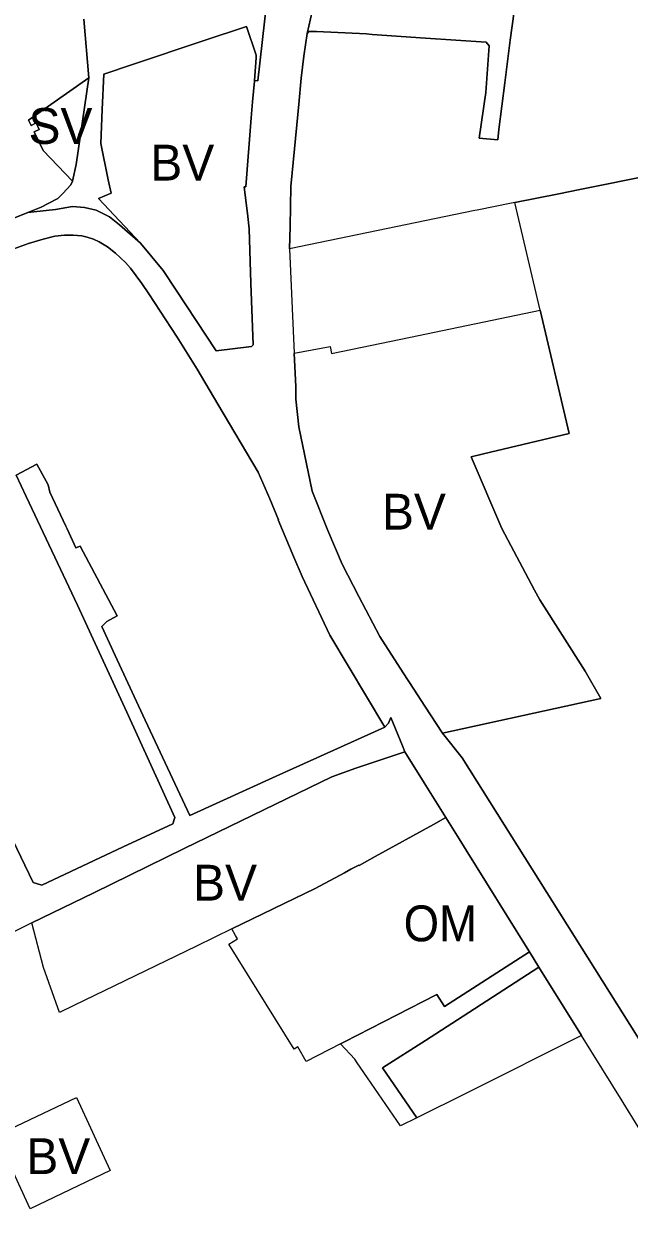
# Model space of a CAD drawing. Extents: x -650451 to -642268, y -1075216 to -1066610.
# Drawn here: x -648281.9 to -648079.4, y -1067506.5 to -1067105.4 of the extents above; entities that cross this region are included whole.
import ezdxf

# ---------------------------------------------------------------- set-up
doc = ezdxf.new("R2010")
doc.units = 0
doc.header["$LTSCALE"] = 4.8
for name, color, linetype, lineweight in [('12', 7, 'Continuous', 13), ('15', 7, 'Continuous', 13), ('19', 7, 'Continuous', 13), ('24', 7, 'Continuous', 13), ('3', 7, 'Continuous', 13), ('46', 7, 'Continuous', 13)]:
    doc.layers.add(name, color=color, linetype=linetype, lineweight=lineweight)
doc.layers.add('62', color=7, linetype='Continuous')

msp = doc.modelspace()

# ---------------------------------------------------------------- linework, layer by layer
at = {"layer": '12'}
for points in [[(-648212.32, -1067408.39), (-648184.44, -1067394.86), (-648174.63, -1067389.58), (-648172.45, -1067388.4), (-648169.81, -1067386.98), (-648169.73, -1067387.11), (-648164.35, -1067384.16), (-648144.8, -1067373.45), (-648140.65, -1067371.06)], [(-648140.65, -1067371.06), (-648136.27, -1067378.19), (-648133.9, -1067381.99), (-648113.46, -1067414.8), (-648112.7, -1067416.03)], [(-648175.94, -1067446.89), (-648187.44, -1067452.8), (-648190.23, -1067447.83), (-648191.46, -1067448.59), (-648213.34, -1067413.46), (-648210.48, -1067411.68), (-648211.08, -1067410.6), (-648212.32, -1067408.39)], [(-648112.7, -1067416.03), (-648141.17, -1067434.4), (-648143.66, -1067430.3), (-648157.23, -1067437.28), (-648174.64, -1067446.22), (-648175.94, -1067446.89)]]:
    msp.add_lwpolyline(points, dxfattribs=at)
at = {"layer": '15'}
msp.add_line((-648187.15, -1067108.56), (-648185.48, -1067101.2), dxfattribs=at)
for points in [[(-648120.26, -1067073.08), (-648118.18, -1067057.64), (-648115.89, -1067041.73), (-648115.37, -1067037.82), (-648109.4, -1067038.4), (-648111.32, -1067052.86), (-648113.21, -1067067.35), (-648115.19, -1067081.63), (-648117.16, -1067096.34), (-648119.2, -1067110.85), (-648121, -1067125.08), (-648122.95, -1067140.69), (-648123.31, -1067144.17), (-648129.51, -1067143.6), (-648127.29, -1067128.4), (-648126.24, -1067112.71), (-648127.23, -1067111.47), (-648147.53, -1067110.1), (-648165.4, -1067108.88), (-648167.25, -1067108.76), (-648183.98, -1067107.89), (-648186.54, -1067107.89), (-648187.15, -1067108.56)], [(-648200.58, -1067097.82), (-648203.67, -1067124.43), (-648204.77, -1067124.3)], [(-648260.23, -1067123.43), (-648261.9, -1067103.74)], [(-648204.77, -1067124.3), (-648204.18, -1067116.76), (-648204.14, -1067115.83), (-648207.42, -1067106.27), (-648221.9, -1067111.09), (-648245.64, -1067119), (-648255.23, -1067122.19), (-648255.75, -1067134.09), (-648256.24, -1067145.39), (-648253.68, -1067157.6), (-648252.74, -1067162.04), (-648257.01, -1067163.83), (-648242.92, -1067178.79), (-648249.92, -1067172.63), (-648253.32, -1067169.98), (-648257.72, -1067167.76), (-648261.61, -1067166.88)], [(-648265.69, -1067158.05), (-648264.39, -1067152.4), (-648260.23, -1067123.43)], [(-648280.63, -1067168.54), (-648276.15, -1067166.76), (-648273.82, -1067165.52), (-648270.63, -1067163.83), (-648268.87, -1067162.19), (-648266.18, -1067159.3), (-648265.69, -1067158.05)], [(-648261.61, -1067166.88), (-648265.72, -1067166.46), (-648271.34, -1067167.56), (-648278.67, -1067168.33), (-648280.63, -1067168.54)], [(-648288.48, -1067372.88), (-648278.83, -1067392.79), (-648275.98, -1067393.72), (-648248.74, -1067380.92), (-648232.11, -1067373.17), (-648231.37, -1067371.1), (-648247.54, -1067335.81), (-648264.05, -1067299.96), (-648281.13, -1067263.61), (-648284.52, -1067256.43), (-648277.56, -1067252.8), (-648273.81, -1067259.75), (-648273.21, -1067262.16), (-648267.92, -1067273.51), (-648267.51, -1067274.4), (-648264.52, -1067280.81), (-648263.08, -1067280.18), (-648250.71, -1067303.55), (-648254.2, -1067305.44), (-648255.84, -1067307.08), (-648251.41, -1067316.83), (-648242.12, -1067336.79), (-648226.42, -1067370.37), (-648197.5, -1067357.28), (-648161.07, -1067340.8)], [(-648161.07, -1067340.8), (-648159.92, -1067339.44), (-648159.09, -1067337.57)], [(-648159.09, -1067337.57), (-648155.18, -1067347.12), (-648154.39, -1067349.06)], [(-648154.39, -1067349.06), (-648170.82, -1067354.57), (-648178.86, -1067357.46), (-648228.27, -1067381.48), (-648258.57, -1067396.29), (-648279.24, -1067406.38), (-648285.08, -1067409.24)], [(-648175.94, -1067446.89), (-648174.64, -1067446.22), (-648157.23, -1067437.28), (-648143.66, -1067430.3), (-648141.17, -1067434.4), (-648112.7, -1067416.03), (-648109.53, -1067421.13)], [(-648109.53, -1067421.13), (-648136.84, -1067438.83), (-648147.52, -1067445.69), (-648161.9, -1067454.92), (-648150.46, -1067471.66)], [(-648150.46, -1067471.66), (-648155.85, -1067474.35), (-648166.97, -1067458.18), (-648170.38, -1067453.23), (-648171.21, -1067452.01), (-648175.94, -1067446.89)]]:
    msp.add_lwpolyline(points, dxfattribs=at)
at = {"layer": '19'}
for points in [[(-648265.69, -1067158.05), (-648275.47, -1067147.81), (-648278.49, -1067141.5), (-648276.78, -1067140.68), (-648277.82, -1067138.52), (-648279.53, -1067139.34), (-648280.36, -1067137.63), (-648260.23, -1067123.43)], [(-648260.23, -1067123.43), (-648264.39, -1067152.4), (-648265.69, -1067158.05)]]:
    msp.add_lwpolyline(points, dxfattribs=at)
at = {"layer": '24'}
for points in [[(-648182.63, -1067072.9), (-648183.67, -1067082.49), (-648183.16, -1067082.6), (-648183.92, -1067088.24), (-648185.48, -1067101.2), (-648187.15, -1067108.56)], [(-648204.77, -1067124.3), (-648203.67, -1067124.43), (-648200.58, -1067097.82)], [(-648187.15, -1067108.56), (-648188.2, -1067116.19), (-648189.09, -1067123.6), (-648189.96, -1067132.29), (-648190.59, -1067139.22), (-648192.56, -1067159.86), (-648192.86, -1067173.21), (-648193.02, -1067180.66), (-648191.439, -1067215.62)], [(-648205.72, -1067213.38), (-648205.23, -1067212.8), (-648205.95, -1067192.14), (-648206.51, -1067174.01), (-648206.95, -1067169.86), (-648208.19, -1067159.9), (-648207.69, -1067159.93), (-648205.81, -1067136.8), (-648205.47, -1067131.51), (-648204.79, -1067124.56), (-648204.77, -1067124.3)], [(-648280.63, -1067168.54), (-648278.67, -1067168.33), (-648271.34, -1067167.56), (-648265.72, -1067166.46), (-648261.61, -1067166.88), (-648257.72, -1067167.76), (-648253.32, -1067169.98), (-648249.92, -1067172.63), (-648242.92, -1067178.79)], [(-648326.59, -1067186.29), (-648324.45, -1067190.09), (-648315.08, -1067184.12), (-648309.13, -1067180.23), (-648305.51, -1067178.42), (-648285.34, -1067170.4), (-648280.63, -1067168.54)], [(-648265.5, -1067176.06), (-648268.35, -1067176.08), (-648271.57, -1067176.46), (-648275.53, -1067177.49), (-648280.44, -1067178.9)], [(-648251.32, -1067182.1), (-648253.95, -1067179.98), (-648256.73, -1067178.33), (-648258.69, -1067177.44), (-648260.74, -1067176.82), (-648262.59, -1067176.38), (-648265.5, -1067176.06)], [(-648280.44, -1067178.9), (-648285.27, -1067180.73), (-648293.08, -1067183.94), (-648299.88, -1067187.36)], [(-648230.62, -1067210.29), (-648240.11, -1067195.76), (-648242.49, -1067192.3), (-648246.3, -1067187.14), (-648247.94, -1067185.21), (-648251.32, -1067182.1)], [(-648242.92, -1067178.79), (-648235.29, -1067187.91), (-648230.97, -1067194.5), (-648217.63, -1067214.84), (-648205.72, -1067213.38)], [(-648196.88, -1067271.44), (-648196.74, -1067271.38), (-648199.6, -1067264.33), (-648203.55, -1067255.48), (-648217.03, -1067232.72), (-648223.9, -1067221.01), (-648230.62, -1067210.29)], [(-648191.439, -1067215.62), (-648190.93, -1067226.88), (-648190.94, -1067231.05), (-648189.95, -1067240.26), (-648185.47, -1067261.84), (-648180.18, -1067274.97), (-648175.38, -1067286.22), (-648169.82, -1067297.07), (-648162.79, -1067310.45), (-648154.99, -1067322.59), (-648151.46, -1067328.15), (-648147.77, -1067333.77), (-648141.82, -1067342.88)], [(-648179.56, -1067310.06), (-648188.84, -1067290.44), (-648191.58, -1067283.96), (-648196.88, -1067271.44)], [(-648161.07, -1067340.8), (-648167.22, -1067330.58), (-648179.56, -1067310.06)], [(-648159.09, -1067337.57), (-648159.92, -1067339.44), (-648161.07, -1067340.8)], [(-648154.39, -1067349.06), (-648155.18, -1067347.12), (-648159.09, -1067337.57)], [(-648141.82, -1067342.88), (-648135.26, -1067351.13), (-648076.68, -1067444.23), (-648047.65, -1067490.38), (-648035.38, -1067509.89), (-648020.26, -1067533.91), (-648017.77, -1067537.87), (-648010.57, -1067549.31), (-647994.8, -1067572.37), (-647969.29, -1067609.79), (-647959.832, -1067623.65)], [(-648140.65, -1067371.06), (-648147.96, -1067359.45), (-648154.39, -1067349.06)], [(-648112.7, -1067416.03), (-648113.46, -1067414.8), (-648133.9, -1067381.99), (-648136.27, -1067378.19), (-648140.65, -1067371.06)], [(-648000.63, -1067599.14), (-648031.77, -1067546.6), (-648045.04, -1067525.15), (-648076.32, -1067474.6), (-648081.31, -1067466.54), (-648081.69, -1067465.92), (-648095.28, -1067444.06), (-648109.53, -1067421.13), (-648112.7, -1067416.03)]]:
    msp.add_lwpolyline(points, dxfattribs=at)
at = {"layer": '3'}
for points in [[(-648001.46, -1066998.45), (-648001.08, -1067010.1), (-648000.66, -1067024.64), (-648000.32, -1067041.95), (-647999.8, -1067060.36), (-647998.47, -1067077.62), (-647998.87, -1067092.57), (-647998.39, -1067108.26), (-647997.86, -1067123.27), (-647997.58, -1067141.08), (-648095.81, -1067160.82), (-648102.92, -1067162.24), (-648117.563, -1067165.191)], [(-648187.15, -1067108.56), (-648186.54, -1067107.89), (-648183.98, -1067107.89), (-648167.25, -1067108.76), (-648165.4, -1067108.88), (-648147.53, -1067110.1), (-648127.23, -1067111.47), (-648126.24, -1067112.71), (-648127.29, -1067128.4), (-648129.51, -1067143.6), (-648123.31, -1067144.17), (-648122.95, -1067140.69), (-648121, -1067125.08), (-648119.2, -1067110.85), (-648117.16, -1067096.34), (-648115.19, -1067081.63), (-648113.21, -1067067.35), (-648111.32, -1067052.86), (-648109.4, -1067038.4), (-648115.37, -1067037.82), (-648115.89, -1067041.73), (-648118.18, -1067057.64), (-648120.26, -1067073.08)], [(-648261.9, -1067103.74), (-648260.23, -1067123.43)], [(-648242.92, -1067178.79), (-648257.01, -1067163.83), (-648252.74, -1067162.04), (-648253.68, -1067157.6), (-648256.24, -1067145.39), (-648255.75, -1067134.09), (-648255.23, -1067122.19), (-648245.64, -1067119), (-648221.9, -1067111.09), (-648207.42, -1067106.27), (-648204.14, -1067115.83), (-648204.18, -1067116.76), (-648204.77, -1067124.3)], [(-648193.02, -1067180.66), (-648192.86, -1067173.21), (-648192.56, -1067159.86), (-648190.59, -1067139.22), (-648189.96, -1067132.29), (-648189.09, -1067123.6), (-648188.2, -1067116.19), (-648187.15, -1067108.56)], [(-648260.23, -1067123.43), (-648280.36, -1067137.63), (-648279.53, -1067139.34), (-648277.82, -1067138.52), (-648276.78, -1067140.68), (-648278.49, -1067141.5), (-648275.47, -1067147.81), (-648265.69, -1067158.05)], [(-648204.77, -1067124.3), (-648204.79, -1067124.56), (-648205.47, -1067131.51), (-648205.81, -1067136.8), (-648207.69, -1067159.93), (-648208.19, -1067159.9), (-648206.95, -1067169.86), (-648206.51, -1067174.01), (-648205.95, -1067192.14), (-648205.23, -1067212.8), (-648205.72, -1067213.38), (-648217.63, -1067214.84), (-648230.97, -1067194.5)], [(-648265.69, -1067158.05), (-648266.18, -1067159.3), (-648268.87, -1067162.19), (-648270.63, -1067163.83), (-648273.82, -1067165.52), (-648276.15, -1067166.76), (-648280.63, -1067168.54), (-648285.34, -1067170.4), (-648305.51, -1067178.42)], [(-648117.563, -1067165.191), (-648118.74, -1067165.43), (-648130.21, -1067167.7), (-648131.01, -1067167.84), (-648193.02, -1067180.66)], [(-648293.08, -1067183.94), (-648285.27, -1067180.73), (-648280.44, -1067178.9), (-648275.53, -1067177.49), (-648271.57, -1067176.46)], [(-648271.57, -1067176.46), (-648268.35, -1067176.08), (-648265.5, -1067176.06), (-648262.59, -1067176.38)], [(-648262.59, -1067176.38), (-648260.74, -1067176.82), (-648258.69, -1067177.44), (-648256.73, -1067178.33), (-648253.95, -1067179.98), (-648251.32, -1067182.1), (-648247.94, -1067185.21), (-648246.3, -1067187.14), (-648242.49, -1067192.3)], [(-648230.97, -1067194.5), (-648235.29, -1067187.91), (-648242.92, -1067178.79)], [(-648242.49, -1067192.3), (-648240.11, -1067195.76), (-648230.62, -1067210.29)], [(-648191.439, -1067215.62), (-648179.42, -1067213.37), (-648179, -1067215.71), (-648152.5, -1067210.23), (-648109.1, -1067201.21)], [(-648109.1, -1067201.21), (-648099.39, -1067242.54), (-648128.08, -1067249.29), (-648132.22, -1067250.27), (-648121.94, -1067274.29), (-648110.97, -1067294.96), (-648109.24, -1067298.21), (-648094.1, -1067322.05), (-648088.84, -1067331.19), (-648141.82, -1067342.88)], [(-648230.62, -1067210.29), (-648223.9, -1067221.01), (-648217.03, -1067232.72), (-648203.55, -1067255.48), (-648199.6, -1067264.33), (-648196.74, -1067271.38), (-648196.88, -1067271.44)], [(-648141.82, -1067342.88), (-648147.77, -1067333.77), (-648151.46, -1067328.15), (-648154.99, -1067322.59), (-648162.79, -1067310.45), (-648169.82, -1067297.07), (-648175.38, -1067286.22), (-648180.18, -1067274.97), (-648185.47, -1067261.84), (-648189.95, -1067240.26), (-648190.94, -1067231.05), (-648190.93, -1067226.88), (-648191.439, -1067215.62)], [(-648161.07, -1067340.8), (-648197.5, -1067357.28), (-648226.42, -1067370.37), (-648242.12, -1067336.79), (-648251.41, -1067316.83), (-648255.84, -1067307.08), (-648254.2, -1067305.44), (-648250.71, -1067303.55), (-648263.08, -1067280.18), (-648264.52, -1067280.81), (-648267.51, -1067274.4), (-648267.92, -1067273.51), (-648273.21, -1067262.16), (-648273.81, -1067259.75), (-648277.56, -1067252.8), (-648284.52, -1067256.43), (-648281.13, -1067263.61), (-648264.05, -1067299.96), (-648247.54, -1067335.81), (-648231.37, -1067371.1), (-648232.11, -1067373.17), (-648248.74, -1067380.92), (-648275.98, -1067393.72), (-648278.83, -1067392.79), (-648288.48, -1067372.88)], [(-648196.88, -1067271.44), (-648191.58, -1067283.96), (-648188.84, -1067290.44), (-648179.56, -1067310.06)], [(-648179.56, -1067310.06), (-648167.22, -1067330.58), (-648161.07, -1067340.8)], [(-648279.24, -1067406.38), (-648258.57, -1067396.29), (-648228.27, -1067381.48), (-648178.86, -1067357.46), (-648170.82, -1067354.57), (-648154.39, -1067349.06)], [(-648154.39, -1067349.06), (-648147.96, -1067359.45), (-648140.65, -1067371.06)], [(-648140.65, -1067371.06), (-648144.8, -1067373.45), (-648164.35, -1067384.16), (-648169.73, -1067387.11), (-648169.81, -1067386.98), (-648172.45, -1067388.4), (-648174.63, -1067389.58), (-648184.44, -1067394.86), (-648212.32, -1067408.39)], [(-648265.197, -1067434.03), (-648270.02, -1067436.37), (-648275.41, -1067421.3), (-648279.24, -1067406.38)], [(-648212.32, -1067408.39), (-648224.19, -1067414.14), (-648265.197, -1067434.03)], [(-648150.46, -1067471.66), (-648161.9, -1067454.92), (-648147.52, -1067445.69), (-648136.84, -1067438.83), (-648109.53, -1067421.13), (-648095.28, -1067444.06)], [(-648095.28, -1067444.06), (-648133.56, -1067463.2), (-648150.46, -1067471.66)]]:
    msp.add_lwpolyline(points, dxfattribs=at)
msp.add_lwpolyline([(-648291.17, -1067477.57), (-648264.34, -1067464.83), (-648253.1, -1067489.23), (-648279.86, -1067502.11)], close=True, dxfattribs=at)
at = {"layer": '46'}
for points in [[(-648117.563, -1067165.191), (-648102.92, -1067162.24), (-648095.81, -1067160.82), (-647997.58, -1067141.08), (-647997.86, -1067123.27), (-647998.39, -1067108.26), (-647998.87, -1067092.57), (-647998.47, -1067077.62), (-647999.8, -1067060.36), (-648000.32, -1067041.95), (-648000.66, -1067024.64), (-648001.08, -1067010.1), (-648001.46, -1066998.45), (-647927.03, -1066978.39)], [(-648141.82, -1067342.88), (-648088.84, -1067331.19), (-648094.1, -1067322.05), (-648109.24, -1067298.21), (-648110.97, -1067294.96), (-648121.94, -1067274.29), (-648132.22, -1067250.27), (-648128.08, -1067249.29), (-648099.39, -1067242.54), (-648109.1, -1067201.21), (-648117.563, -1067165.191)], [(-647969.29, -1067609.79), (-647994.8, -1067572.37), (-648010.57, -1067549.31), (-648017.77, -1067537.87), (-648020.26, -1067533.91), (-648035.38, -1067509.89), (-648047.65, -1067490.38), (-648076.68, -1067444.23), (-648135.26, -1067351.13), (-648141.82, -1067342.88)]]:
    msp.add_lwpolyline(points, dxfattribs=at)

# ---------------------------------------------------------------- texts
at = {"layer": '62'}
for s, p in [('SV', (-648280.404, -1067145.541)), ('BV', (-648239.618, -1067157.827)), ('BV', (-648162.087, -1067274.696)), ('BV', (-648225.305, -1067398.895)), ('BV', (-648281.125, -1067490.455))]:
    msp.add_text(s, height=12, dxfattribs=at).set_placement(p)
at = {"layer": '62', "width": 0.95}
msp.add_text('OM', height=12, dxfattribs=at).set_placement((-648154.813, -1067412.52))

doc.saveas('drawing.dxf')
